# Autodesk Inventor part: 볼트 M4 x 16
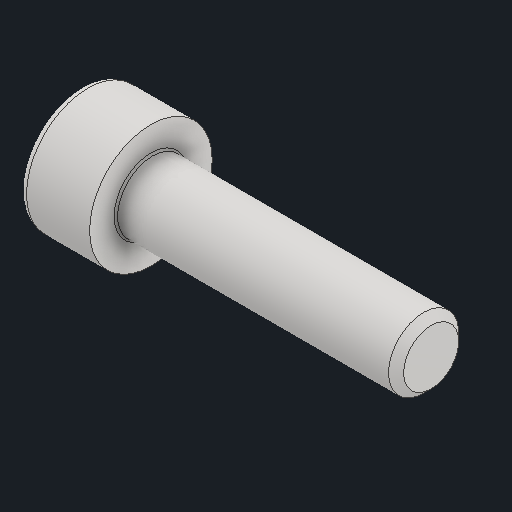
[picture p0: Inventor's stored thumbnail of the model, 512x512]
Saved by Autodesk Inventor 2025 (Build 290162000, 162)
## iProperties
Created: 2025-08
Part Number: 볼트 M4 x 16
Material: 스테인리스강
Description: 6각 소켓 머리 캡 나사
Document SubType Name: Modeling
Designer: infra11
Density: 8.08 g/cm^3
Appearance: 기본값
Author: jhkim
Sending System: Autodesk Inventor 2026
Preprocessor: ST-DEVELOPER v20.1
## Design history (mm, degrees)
feature "Solid1"
node "솔리드1"
